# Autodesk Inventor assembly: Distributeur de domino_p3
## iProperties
Shininess: 41.0
Length Units: 11269
Angle Units: 11279
Time Units: 11290
Mass Units: 11283
Length Display Precision: 3
Angle Display Precision: 2
Created: 2002-05
Part Number: Distributeur de domino_p3
Document SubType Name: Assemblage
Designer: Flavien MARTY
Density: 0.0
Volumn: 0.0
Area: 0.0
PropertySet Name: Model Information
Control State: 0
Master: False
Checked Out: False
Author: Flavien MARTY
